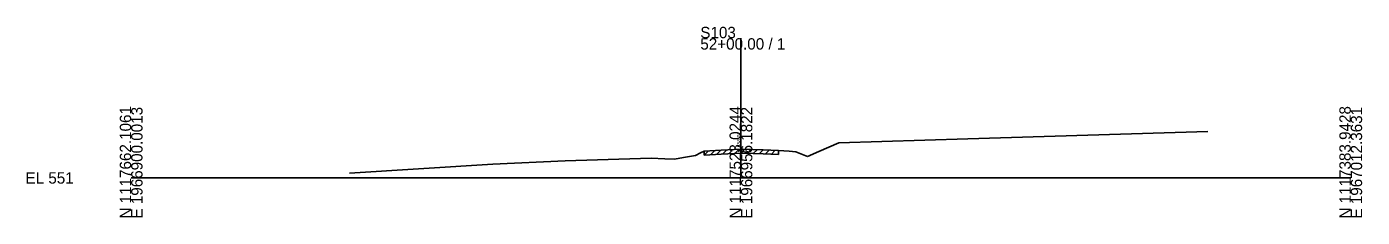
# Model space of a CAD drawing. Extents: x 974 to 1303, y 990 to 14518.
# Drawn here: x 974.3 to 1302.8, y 1990.3 to 2037.2 of the extents above; entities that cross this region are included whole.
import ezdxf

# ---------------------------------------------------------------- set-up
doc = ezdxf.new("R2010")
doc.units = 0
for name, color, linetype in [('Level 10', 7, 'Continuous'), ('Level 60', 7, 'Continuous'), ('Level 61', 7, 'Continuous'), ('Level 63', 7, 'Continuous')]:
    doc.layers.add(name, color=color, linetype=linetype)

msp = doc.modelspace()

# ---------------------------------------------------------------- linework, layer by layer
at = {"layer": 'Level 60'}
for p, q in [((1205.79, 2009.61), (1264.87, 2011.47)), ((1169.19, 2006.49), (1174.1, 2008.61)), ((1174.1, 2008.61), (1205.79, 2009.61)), ((1088.93, 2003.4), (1106.78, 2004.22)), ((1106.78, 2004.22), (1114.69, 2004.45)), ((1114.69, 2004.45), (1127.92, 2004.85)), ((1127.92, 2004.85), (1131.31, 2004.69)), ((1131.31, 2004.69), (1133.67, 2004.61)), ((1133.67, 2004.61), (1135.87, 2005)), ((1135.87, 2005), (1138.79, 2005.51)), ((1138.79, 2005.51), (1140.06, 2006.19)), ((1140.06, 2006.19), (1140.99, 2006.61)), ((1140.99, 2006.61), (1145.14, 2006.83)), ((1145.14, 2006.83), (1150, 2007.07)), ((1150, 2007.07), (1150.44, 2007.09)), ((1150.44, 2007.09), (1155.43, 2006.91)), ((1155.43, 2006.91), (1159.23, 2006.78)), ((1159.23, 2006.78), (1161.9, 2006.56)), ((1161.9, 2006.56), (1163.5, 2006.43)), ((1163.5, 2006.43), (1164.7, 2005.97)), ((1164.7, 2005.97), (1166.41, 2005.28)), ((1166.41, 2005.28), (1169.19, 2006.49)), ((1053.71, 2001.14), (1088.93, 2003.4))]:
    msp.add_line(p, q, dxfattribs=at)
at = {"layer": 'Level 61'}
for p, q in [((1140.99, 2005.61), (1142.04, 2006.66)), ((1140.99, 2005.61), (1140.99, 2006.61)), ((1140.99, 2005.61), (1145.14, 2005.83)), ((1140.99, 2005.61), (1140.99, 2005.61)), ((1142.49, 2005.69), (1143.54, 2006.74)), ((1143.99, 2005.77), (1145.04, 2006.82)), ((1145.14, 2005.83), (1150, 2006.07)), ((1145.49, 2005.84), (1146.54, 2006.9)), ((1146.99, 2005.92), (1148.04, 2006.97)), ((1148.49, 2005.99), (1149.54, 2007.05)), ((1149.99, 2006.07), (1150.99, 2007.07)), ((1150, 2006.07), (1150.44, 2006.09)), ((1150.44, 2006.09), (1155.43, 2005.91)), ((1151.49, 2006.05), (1152.45, 2007.02)), ((1152.99, 2006), (1153.95, 2006.96)), ((1154.49, 2005.94), (1155.45, 2006.91)), ((1155.43, 2005.91), (1159.23, 2005.78)), ((1155.99, 2005.89), (1156.95, 2006.86)), ((1157.49, 2005.84), (1158.45, 2006.8)), ((1159.23, 2006.78), (1159.23, 2005.78))]:
    msp.add_line(p, q, dxfattribs=at)
at = {"layer": 'Level 63'}
for p, q in [((1150, 2000), (1150, 2034.4)), ((1000, 2000), (1150, 2000)), ((1150, 2000), (1300, 2000))]:
    msp.add_line(p, q, dxfattribs=at)

# ---------------------------------------------------------------- texts
at = {"layer": 'Level 10'}
msp.add_text('558.07', height=0.9, rotation=90, dxfattribs=at).set_placement((1149.95, 2007.57))
at = {"layer": 'Level 63'}
for s, p in [('S103', (1140, 2034.4)), ('52+00.00 / 1', (1140, 2031.6)), ('EL 551', (974, 1998.6))]:
    msp.add_text(s, height=2.8, dxfattribs=at).set_placement(p)
for s, p in [('N 1117662.1061', (1000, 1990)), ('E 1966900.0013', (1002.8, 1990)), ('N 1117523.0244', (1150, 1990)), ('E 1966956.1822', (1152.8, 1990)), ('N 1117383.9428', (1300, 1990)), ('E 1967012.3631', (1302.8, 1990))]:
    msp.add_text(s, height=2.8, rotation=90, dxfattribs=at).set_placement(p)

doc.saveas('drawing.dxf')
